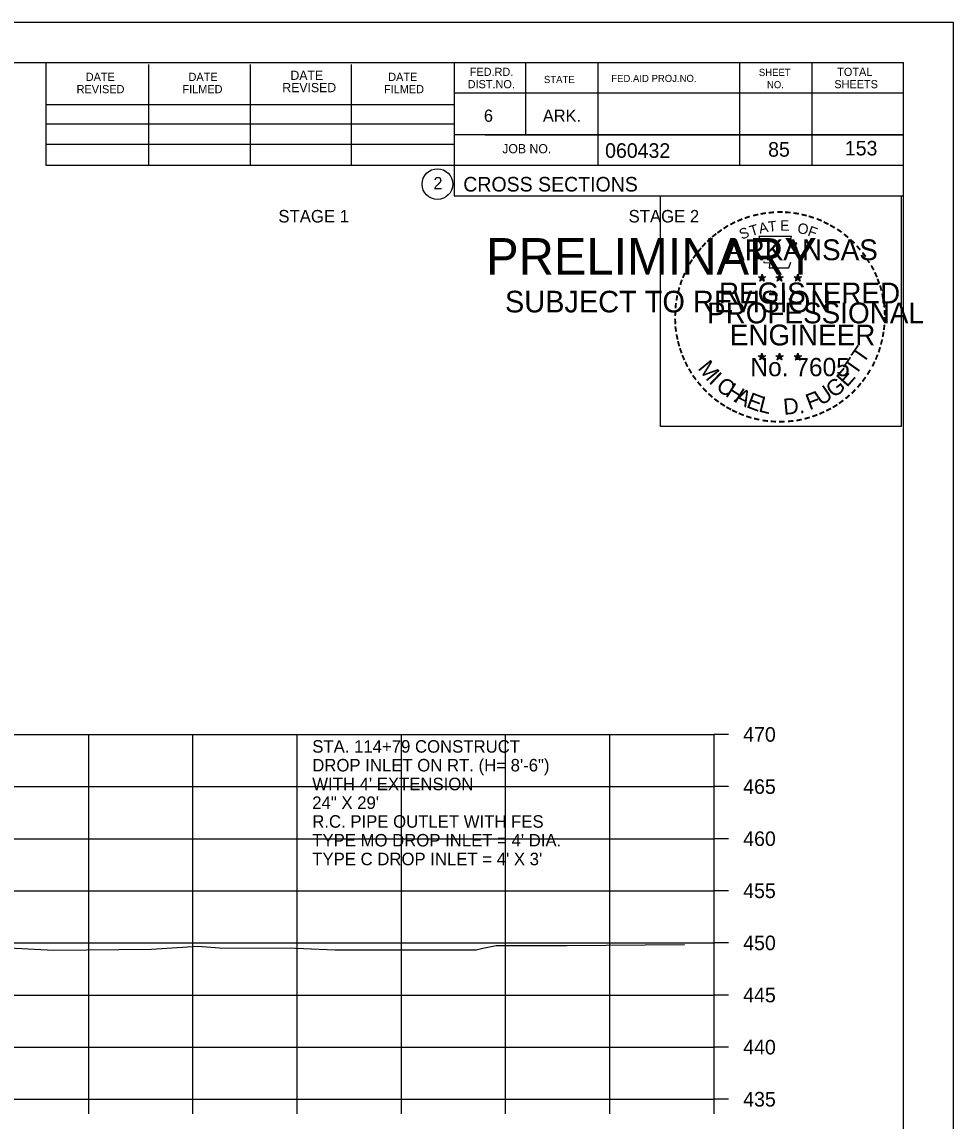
# Model space of a CAD drawing. Extents: x 1538688 to 1540766, y 656250 to 671912.
# Drawn here: x 1538931.8 to 1539021.1, y 658579.2 to 658684.6 of the extents above; entities that cross this region are included whole.
import ezdxf

# ---------------------------------------------------------------- set-up
doc = ezdxf.new("R2010")
doc.units = 0
for name, color, linetype in [('18', 7, 'Continuous'), ('22', 7, 'Continuous'), ('26', 7, 'Continuous'), ('40', 7, 'Continuous'), ('7', 7, 'Continuous'), ('8', 7, 'Continuous'), ('9', 7, 'Continuous'), ('Borings', 7, 'Continuous'), ('Default', 7, 'Continuous'), ('Horizontal Alignment', 7, 'Continuous'), ('RipRap', 7, 'Continuous')]:
    doc.layers.add(name, color=color, linetype=linetype)

msp = doc.modelspace()

# ---------------------------------------------------------------- linework, layer by layer
at = {"layer": '18'}
msp.add_lwpolyline([(1538918.78, 658596.39), (1538934.84, 658595.56), (1538944.21, 658595.67), (1538948.66, 658595.95), (1538950.74, 658595.79), (1538958.02, 658595.75), (1538961.83, 658595.6), (1538975.36, 658595.59), (1538976.01, 658595.74), (1538977.28, 658596.02), (1538984.07, 658596), (1538995.33, 658596.11)], dxfattribs=at)
at = {"layer": '22'}
for p, q in [((1538718.18, 658616.26), (1538998.18, 658616.26)), ((1538938.18, 658581.26), (1538938.18, 658616.26)), ((1538948.18, 658581.26), (1538948.18, 658616.26)), ((1538958.18, 658581.26), (1538958.18, 658616.26)), ((1538968.18, 658581.26), (1538968.18, 658616.26)), ((1538978.18, 658581.26), (1538978.18, 658616.26)), ((1538988.18, 658581.26), (1538988.18, 658616.26)), ((1538998.18, 658581.26), (1538998.18, 658616.26)), ((1538718.18, 658611.26), (1538998.18, 658611.26)), ((1538718.18, 658606.26), (1538998.18, 658606.26)), ((1538718.18, 658601.26), (1538998.18, 658601.26)), ((1538718.18, 658596.26), (1538998.18, 658596.26)), ((1538718.18, 658591.26), (1538998.18, 658591.26)), ((1538718.18, 658586.26), (1538998.18, 658586.26)), ((1538718.18, 658581.26), (1538998.18, 658581.26))]:
    msp.add_line(p, q, dxfattribs=at)
at = {"layer": '26'}
msp.add_line((1538687.78, 658684.61), (1539021.11, 658684.61), dxfattribs=at)
for points in [[(1538687.77, 658684.61), (1539021.11, 658684.61), (1539021.11, 658471.28), (1538687.77, 658471.28)], [(1538993.03, 658667.95), (1539016.13, 658667.95), (1539016.13, 658645.8), (1538993.03, 658645.8)]]:
    msp.add_lwpolyline(points, close=True, dxfattribs=at)
at = {"layer": '8'}
for p, q in [((1539002.44, 658660.17), (1539002.79, 658660.06)), ((1539002.44, 658660.17), (1539002.69, 658660.12)), ((1539002.44, 658660.17), (1539002.68, 658660.04)), ((1539002.57, 658659.76), (1539002.79, 658660.06)), ((1539002.57, 658659.76), (1539002.7, 658660)), ((1539002.57, 658659.76), (1539002.79, 658659.98)), ((1539002.79, 658660.42), (1539002.75, 658660.17)), ((1539002.79, 658660.06), (1539002.79, 658660.42)), ((1539002.79, 658660.42), (1539002.84, 658660.17)), ((1539003.13, 658660.17), (1539002.79, 658660.06)), ((1539003, 658659.76), (1539002.79, 658660.06)), ((1539003, 658659.76), (1539002.79, 658659.97)), ((1539003.13, 658660.17), (1539002.85, 658660.12)), ((1539003, 658659.76), (1539002.86, 658660.05)), ((1539003.13, 658660.17), (1539002.93, 658660.06)), ((1539004.11, 658660.17), (1539004.46, 658660.06)), ((1539004.11, 658660.17), (1539004.36, 658660.12)), ((1539004.11, 658660.17), (1539004.35, 658660.04)), ((1539004.24, 658659.76), (1539004.46, 658660.06)), ((1539004.24, 658659.76), (1539004.37, 658660)), ((1539004.24, 658659.76), (1539004.46, 658659.98)), ((1539004.46, 658660.42), (1539004.42, 658660.17)), ((1539004.46, 658660.06), (1539004.46, 658660.42)), ((1539004.46, 658660.42), (1539004.51, 658660.17)), ((1539004.8, 658660.17), (1539004.46, 658660.06)), ((1539004.67, 658659.76), (1539004.46, 658660.06)), ((1539004.67, 658659.76), (1539004.46, 658659.97)), ((1539004.8, 658660.17), (1539004.52, 658660.12)), ((1539004.67, 658659.76), (1539004.53, 658660.05)), ((1539004.8, 658660.17), (1539004.6, 658660.06)), ((1539005.87, 658660.15), (1539006.22, 658660.04)), ((1539005.87, 658660.15), (1539006.13, 658660.11)), ((1539005.87, 658660.15), (1539006.11, 658660.03)), ((1539006.01, 658659.75), (1539006.22, 658660.04)), ((1539006.01, 658659.75), (1539006.13, 658659.99)), ((1539006.01, 658659.75), (1539006.22, 658659.96)), ((1539006.22, 658660.41), (1539006.18, 658660.16)), ((1539006.22, 658660.04), (1539006.22, 658660.41)), ((1539006.22, 658660.41), (1539006.27, 658660.16)), ((1539006.57, 658660.15), (1539006.22, 658660.04)), ((1539006.43, 658659.75), (1539006.22, 658660.04)), ((1539006.43, 658659.75), (1539006.22, 658659.96)), ((1539006.57, 658660.15), (1539006.28, 658660.11)), ((1539006.43, 658659.75), (1539006.3, 658660.04)), ((1539006.57, 658660.15), (1539006.36, 658660.05)), ((1539002.43, 658652.59), (1539002.78, 658652.48)), ((1539002.43, 658652.59), (1539002.69, 658652.55)), ((1539002.43, 658652.59), (1539002.67, 658652.47)), ((1539002.57, 658652.19), (1539002.78, 658652.48)), ((1539002.57, 658652.19), (1539002.69, 658652.43)), ((1539002.57, 658652.19), (1539002.78, 658652.4)), ((1539002.78, 658652.85), (1539002.74, 658652.6)), ((1539002.78, 658652.48), (1539002.78, 658652.85)), ((1539002.78, 658652.85), (1539002.83, 658652.6)), ((1539003.13, 658652.59), (1539002.78, 658652.48)), ((1539003, 658652.19), (1539002.78, 658652.48)), ((1539003, 658652.19), (1539002.78, 658652.4)), ((1539003.13, 658652.59), (1539002.84, 658652.54)), ((1539003, 658652.19), (1539002.86, 658652.48)), ((1539003.13, 658652.59), (1539002.93, 658652.49)), ((1539004.1, 658652.59), (1539004.45, 658652.48)), ((1539004.1, 658652.59), (1539004.36, 658652.55)), ((1539004.1, 658652.59), (1539004.34, 658652.47)), ((1539004.24, 658652.19), (1539004.45, 658652.48)), ((1539004.24, 658652.19), (1539004.36, 658652.43)), ((1539004.24, 658652.19), (1539004.45, 658652.4)), ((1539004.45, 658652.85), (1539004.41, 658652.6)), ((1539004.45, 658652.48), (1539004.45, 658652.85)), ((1539004.45, 658652.85), (1539004.5, 658652.6)), ((1539004.8, 658652.59), (1539004.45, 658652.48)), ((1539004.67, 658652.19), (1539004.45, 658652.48)), ((1539004.67, 658652.19), (1539004.45, 658652.4)), ((1539004.8, 658652.59), (1539004.51, 658652.54)), ((1539004.67, 658652.19), (1539004.53, 658652.48)), ((1539004.8, 658652.59), (1539004.6, 658652.49)), ((1539005.87, 658652.58), (1539006.22, 658652.47)), ((1539005.87, 658652.58), (1539006.12, 658652.54)), ((1539005.87, 658652.58), (1539006.11, 658652.46)), ((1539006, 658652.18), (1539006.22, 658652.47)), ((1539006, 658652.18), (1539006.13, 658652.42)), ((1539006, 658652.18), (1539006.22, 658652.39)), ((1539006.22, 658652.84), (1539006.18, 658652.59)), ((1539006.22, 658652.47), (1539006.22, 658652.84)), ((1539006.22, 658652.84), (1539006.27, 658652.59)), ((1539006.57, 658652.58), (1539006.22, 658652.47)), ((1539006.43, 658652.18), (1539006.22, 658652.47)), ((1539006.43, 658652.18), (1539006.22, 658652.39)), ((1539006.57, 658652.58), (1539006.28, 658652.53)), ((1539006.43, 658652.18), (1539006.3, 658652.47)), ((1539006.57, 658652.58), (1539006.36, 658652.48))]:
    msp.add_line(p, q, dxfattribs=at)
for points in [[(1539002.48, 658664.04), (1539002.75, 658663.22)], [(1539005.99, 658663.12), (1539006.13, 658663.41), (1539005.45, 658663.38), (1539005.6, 658664.04), (1539002.48, 658664.04)], [(1539002.97, 658661.62), (1539002.97, 658661.53), (1539003.53, 658661.52), (1539003.48, 658661.04), (1539005.35, 658661.04), (1539005.55, 658661.58)], [(1539002.79, 658660.42), (1539003, 658659.76), (1539002.44, 658660.17), (1539003.13, 658660.17), (1539002.57, 658659.76), (1539002.79, 658660.42)], [(1539004.46, 658660.42), (1539004.67, 658659.76), (1539004.11, 658660.17), (1539004.8, 658660.17), (1539004.24, 658659.76), (1539004.46, 658660.42)], [(1539006.22, 658660.41), (1539006.43, 658659.75), (1539005.87, 658660.15), (1539006.57, 658660.15), (1539006.01, 658659.75), (1539006.22, 658660.41)], [(1539002.78, 658652.85), (1539003, 658652.19), (1539002.43, 658652.59), (1539003.13, 658652.59), (1539002.57, 658652.19), (1539002.78, 658652.85)], [(1539004.45, 658652.85), (1539004.67, 658652.19), (1539004.1, 658652.59), (1539004.8, 658652.59), (1539004.24, 658652.19), (1539004.45, 658652.85)], [(1539006.22, 658652.84), (1539006.43, 658652.18), (1539005.87, 658652.58), (1539006.57, 658652.58), (1539006, 658652.18), (1539006.22, 658652.84)]]:
    msp.add_lwpolyline(points, dxfattribs=at)
for centre, radius in [((1539002.79, 658660.06), 0.172), ((1539002.79, 658660.06), 0.145), ((1539002.79, 658660.06), 0.116), ((1539002.79, 658660.06), 0.0991), ((1539002.79, 658660.06), 0.0747), ((1539002.79, 658660.06), 0.0495), ((1539002.79, 658660.06), 0.0296), ((1539004.46, 658660.06), 0.172), ((1539004.46, 658660.06), 0.145), ((1539004.46, 658660.06), 0.116), ((1539004.46, 658660.06), 0.0991), ((1539004.46, 658660.06), 0.0747), ((1539004.46, 658660.06), 0.0495), ((1539004.46, 658660.06), 0.0296), ((1539006.22, 658660.04), 0.172), ((1539006.22, 658660.04), 0.145), ((1539006.22, 658660.04), 0.116), ((1539006.22, 658660.04), 0.0991), ((1539006.22, 658660.04), 0.0747), ((1539006.22, 658660.04), 0.0495), ((1539006.22, 658660.04), 0.0296), ((1539002.78, 658652.48), 0.172), ((1539002.78, 658652.48), 0.145), ((1539002.78, 658652.48), 0.116), ((1539002.78, 658652.48), 0.0991), ((1539002.78, 658652.48), 0.0747), ((1539002.78, 658652.48), 0.0495), ((1539002.78, 658652.48), 0.0296), ((1539004.45, 658652.48), 0.172), ((1539004.45, 658652.48), 0.145), ((1539004.45, 658652.48), 0.116), ((1539004.45, 658652.48), 0.0991), ((1539004.45, 658652.48), 0.0747), ((1539004.45, 658652.48), 0.0495), ((1539004.45, 658652.48), 0.0296), ((1539006.22, 658652.47), 0.172), ((1539006.22, 658652.47), 0.145), ((1539006.22, 658652.47), 0.116), ((1539006.22, 658652.47), 0.0991), ((1539006.22, 658652.47), 0.0747), ((1539006.22, 658652.47), 0.0495), ((1539006.22, 658652.47), 0.0296)]:
    msp.add_circle(centre, radius, dxfattribs=at)
at = {"layer": 'Borings'}
for p, q in [((1538998.18, 658581.26), (1538998.18, 658616.26)), ((1538999.58, 658616.26), (1538998.18, 658616.26)), ((1538999.58, 658611.26), (1538998.18, 658611.26)), ((1538999.58, 658606.26), (1538998.18, 658606.26)), ((1538999.58, 658601.26), (1538998.18, 658601.26)), ((1538999.58, 658596.26), (1538998.18, 658596.26)), ((1538999.58, 658591.26), (1538998.18, 658591.26)), ((1538999.58, 658586.26), (1538998.18, 658586.26)), ((1538718.18, 658581.26), (1538998.18, 658581.26)), ((1538938.18, 658579.86), (1538938.18, 658581.26)), ((1538948.18, 658579.86), (1538948.18, 658581.26)), ((1538958.18, 658579.86), (1538958.18, 658581.26)), ((1538968.18, 658579.86), (1538968.18, 658581.26)), ((1538978.18, 658579.86), (1538978.18, 658581.26)), ((1538988.18, 658579.86), (1538988.18, 658581.26)), ((1538998.18, 658579.86), (1538998.18, 658581.26)), ((1538999.58, 658581.26), (1538998.18, 658581.26))]:
    msp.add_line(p, q, dxfattribs=at)
at = {"layer": 'RipRap'}
for p, q in [((1538700.18, 658680.72), (1539016.36, 658680.72)), ((1538934.1, 658670.84), (1538934.1, 658680.72)), ((1538973.26, 658680.72), (1538973.26, 658667.92)), ((1538980.1, 658680.72), (1538980.1, 658673.78)), ((1538987.04, 658680.72), (1538987.04, 658670.84)), ((1539000.62, 658680.72), (1539000.62, 658670.84)), ((1539007.56, 658680.72), (1539007.56, 658670.84)), ((1539016.36, 658475.26), (1539016.36, 658680.72)), ((1538943.96, 658670.84), (1538943.96, 658680.52)), ((1538953.72, 658670.84), (1538953.72, 658680.52)), ((1538963.4, 658670.84), (1538963.4, 658680.52)), ((1539016.36, 658677.78), (1538973.26, 658677.78)), ((1539016.36, 658677.8), (1539016.36, 658677.8)), ((1538934.1, 658676.7), (1538973.26, 658676.7)), ((1538934.1, 658674.84), (1538973.26, 658674.84)), ((1539016.36, 658673.78), (1538973.26, 658673.78)), ((1538976.22, 658673.78), (1539016.36, 658673.78)), ((1538934.1, 658670.84), (1538934.1, 658672.9)), ((1538934.1, 658672.9), (1538973.26, 658672.9)), ((1539016.36, 658670.84), (1538934.1, 658670.84)), ((1538973.26, 658667.92), (1539016.36, 658667.92))]:
    msp.add_line(p, q, dxfattribs=at)
msp.add_circle((1538971.64, 658669.06), 1.47, dxfattribs=at)

# ---------------------------------------------------------------- texts
at = {"layer": '40'}
for s, p in [('STA. 114+79 CONSTRUCT', (1538959.63, 658614.51)), ('DROP INLET ON RT. (H= 8\'-6") ', (1538959.63, 658612.71)), ("WITH 4' EXTENSION ", (1538959.63, 658610.91)), ('24" X 29\'', (1538959.63, 658609.11)), ('R.C. PIPE OUTLET WITH FES', (1538959.63, 658607.31)), ("TYPE MO DROP INLET = 4' DIA.", (1538959.63, 658605.51)), ("TYPE C DROP INLET = 4' X 3'", (1538959.63, 658603.71))]:
    msp.add_text(s, height=1.2, dxfattribs=at).set_placement(p)
at = {"layer": '7'}
for s, p in [('153', (1539010.73, 658671.81)), ('85', (1539003.37, 658671.69))]:
    msp.add_text(s, height=1.4, dxfattribs=at).set_placement(p)
at = {"layer": '8'}
for s, height, rotation, p in [('-', 1.6, 24.3072, (1539000.59, 658664.9)), ('-', 1.6, 19.1761, (1539001.23, 658665.17)), ('-', 1.6, 13.6301, (1539001.98, 658665.41)), ('-', 1.6, 10.2193, (1539002.66, 658665.57)), ('-', 1.6, 5.8968, (1539003.38, 658665.68)), ('-', 1.6, 0.1862, (1539004.16, 658665.76)), ('-', 1.6, 357.743, (1539004.88, 658665.74)), ('-', 1.6, 352.1617, (1539005.62, 658665.69)), ('-', 1.6, 347.2049, (1539006.34, 658665.57)), ('-', 1.6, 342.3362, (1539006.98, 658665.42)), ('-', 1.6, 337.8551, (1539007.71, 658665.2)), ('-', 1.6, 36.2317, (1538998.79, 658663.82)), ('-', 1.6, 34.0636, (1538999.36, 658664.22)), ('-', 1.6, 28.7918, (1538999.96, 658664.59)), ('S', 1, 21.594, (1539000.83, 658663.72)), ('T', 1, 16.4036, (1539001.75, 658664.05)), ('A', 1, 11.2132, (1539002.57, 658664.3)), ('T', 1, 6.0228, (1539003.42, 658664.47)), ('E', 1, 0.8323, (1539004.53, 658664.58)), ('O', 1, 350.4515, (1539006.13, 658664.37)), ('F', 1, 340.0707, (1539007.09, 658664.14)), ('-', 1.6, 334.1211, (1539008.34, 658664.92)), ('-', 1.6, 329.6409, (1539008.92, 658664.64)), ('-', 1.6, 325.8627, (1539009.57, 658664.28)), ('-', 1.6, 42.9622, (1538997.88, 658663.03)), ('-', 1.6, 38.9507, (1538998.31, 658663.44)), ('ARKANSAS', 2, 360, (1538999.33, 658661.76)), ('-', 1.6, 320.5297, (1539010.18, 658663.85)), ('-', 1.6, 315.5786, (1539010.77, 658663.37)), ('-', 1.6, 50.6142, (1538997.03, 658662.06)), ('-', 1.6, 48.423, (1538997.43, 658662.55)), ('-', 1.6, 309.8797, (1539011.34, 658662.82)), ('-', 1.6, 58.0706, (1538996.29, 658660.97)), ('-', 1.6, 54.2325, (1538996.61, 658661.49)), ('-', 1.6, 306.6522, (1539011.87, 658662.21)), ('-', 1.4, 303.6753, (1539012.35, 658661.65)), ('-', 1.6, 67.7743, (1538995.72, 658659.74)), ('-', 1.6, 62.8713, (1538995.97, 658660.35)), ('-', 1.6, 299.6684, (1539012.67, 658661.04)), ('-', 1.6, 294.6628, (1539013, 658660.43)), ('-', 1.6, 72.3945, (1538995.5, 658659.11)), ('REGISTERED', 2, 360, (1538998.65, 658657.61)), ('DWB', 0.01, 360, (1539002.77, 658660.05)), ('DWB', 0.01, 360, (1539004.44, 658660.05)), ('DWB', 0.01, 360, (1539006.21, 658660.04)), ('-', 1.6, 290.5728, (1539013.25, 658659.85)), ('-', 1.6, 75.461, (1538995.3, 658658.4)), ('-', 1.6, 285.1233, (1539013.49, 658659.27)), ('-', 1.6, 280.5493, (1539013.69, 658658.53)), ('-', 1.6, 85.1863, (1538995.09, 658656.99)), ('-', 1.6, 81.2013, (1538995.17, 658657.69)), ('PROFESSIONAL', 2, 360, (1538997.51, 658655.7)), ('-', 1.6, 276.5962, (1539013.85, 658657.76)), ('-', 1.6, 89.0622, (1538995.07, 658656.29)), ('-', 1.6, 274.3301, (1539013.91, 658657.04)), ('-', 1.6, 269.9407, (1539013.94, 658656.41)), ('-', 1.6, 94.1959, (1538995.1, 658655.57)), ('-', 1.6, 98.9479, (1538995.17, 658654.9)), ('ENGINEER', 2, 360, (1538999.69, 658653.58)), ('-', 1.6, 263.5172, (1539013.93, 658655.74)), ('-', 1.6, 101.7149, (1538995.31, 658654.17)), ('-', 1.6, 260.9953, (1539013.85, 658655.09)), ('-', 1.6, 105.4578, (1538995.47, 658653.57)), ('-', 1.6, 109.0874, (1538995.69, 658652.94)), ('T', 1.54, 55.055, (1539012.5, 658651.75)), ('-', 1.6, 252.8681, (1539013.56, 658653.69)), ('-', 1.6, 255.7626, (1539013.74, 658654.41)), ('-', 1.6, 114.0643, (1538995.94, 658652.35)), ('M', 1.54, 308.9175, (1538996.55, 658651.37)), ('No. 7605', 1.757, 360, (1539001.67, 658650.63)), ('DWB', 0.01, 360, (1539002.77, 658652.48)), ('DWB', 0.01, 360, (1539004.44, 658652.48)), ('DWB', 0.01, 360, (1539006.2, 658652.47)), ('T', 1.54, 55.055, (1539011.77, 658650.63)), ('-', 1.6, 247.8887, (1539013.34, 658653.02)), ('-', 1.6, 115.7289, (1538996.24, 658651.73)), ('-', 1.6, 120.4471, (1538996.6, 658651.14)), ('I', 1.54, 316.4636, (1538997.6, 658650.05)), ('E', 1.54, 48.7313, (1539010.93, 658649.5)), ('-', 1.6, 239.0712, (1539012.68, 658651.63)), ('-', 1.6, 244.6197, (1539013.08, 658652.39)), ('-', 1.6, 125.8934, (1538997, 658650.58)), ('-', 1.6, 130.7181, (1538997.47, 658650.03)), ('C', 1.54, 324.0197, (1538998.27, 658649.43)), ('H', 1.54, 327.5342, (1538999.18, 658648.78)), ('G', 1.54, 38.2173, (1539009.67, 658648.48)), ('-', 1.6, 231.2538, (1539011.85, 658650.42)), ('-', 1.6, 233.8452, (1539012.28, 658650.98)), ('-', 1.6, 134.2238, (1538997.98, 658649.48)), ('-', 1.6, 138.9338, (1538998.51, 658649.02)), ('A', 1.54, 332.5513, (1539000.03, 658648.24)), ('E', 1.54, 339.2068, (1539001.19, 658647.68)), ('F', 1.54, 20.8202, (1539007.34, 658647.35)), ('U', 1.54, 34.4052, (1539008.47, 658647.75)), ('-', 1.6, 225.7653, (1539011.37, 658649.85)), ('-', 1.6, 144.6463, (1538999.06, 658648.61)), ('-', 1.6, 148.0898, (1538999.63, 658648.24)), ('L', 1.54, 346.2929, (1539002.38, 658647.25)), ('D.', 1.54, 5.2602, (1539004.89, 658646.92)), ('-', 1.6, 212.2491, (1539009.77, 658648.48)), ('-', 1.6, 215.7363, (1539010.3, 658648.87)), ('-', 1.6, 221.0851, (1539010.85, 658649.34)), ('-', 1.6, 151.5704, (1539000.2, 658647.92)), ('-', 1.6, 154.6002, (1539000.73, 658647.67)), ('-', 1.6, 158.5612, (1539001.35, 658647.42)), ('-', 1.6, 162.7983, (1539002.04, 658647.2)), ('-', 1.6, 200.7184, (1539007.97, 658647.55)), ('-', 1.6, 204.2516, (1539008.59, 658647.82)), ('-', 1.6, 207.3568, (1539009.21, 658648.14)), ('-', 1.6, 167.5555, (1539002.75, 658647.04)), ('-', 1.6, 173.1155, (1539003.52, 658646.93)), ('-', 1.6, 176.5183, (1539004.27, 658646.88)), ('-', 1.6, 181.5918, (1539005.02, 658646.9)), ('-', 1.6, 185.8167, (1539005.83, 658646.97)), ('-', 1.6, 191.2858, (1539006.56, 658647.1)), ('-', 1.6, 195.4743, (1539007.29, 658647.3))]:
    msp.add_text(s, height=height, rotation=rotation, dxfattribs=at).set_placement(p)
at = {"layer": '9'}
for s, height, p in [('PRELIMINARY', 3.5, (1538976.31, 658660.38)), ('DWB', 0.01, (1538977.06, 658662.23)), ('SUBJECT TO REVISION', 2.0751, (1538978.12, 658656.75))]:
    msp.add_text(s, height=height, rotation=360, dxfattribs=at).set_placement(p)
at = {"layer": 'Default'}
for s, p in [('STAGE 1', (1538956.38, 658665.38)), ('STAGE 2', (1538989.98, 658665.38))]:
    msp.add_text(s, height=1.2, dxfattribs=at).set_placement(p)
at = {"layer": 'Horizontal Alignment'}
for s, p in [('470', (1539000.98, 658615.56)), ('465', (1539000.98, 658610.56)), ('460', (1539000.98, 658605.56)), ('455', (1539000.98, 658600.56)), ('450', (1539000.98, 658595.56)), ('445', (1539000.98, 658590.56)), ('440', (1539000.98, 658585.56)), ('435', (1539000.98, 658580.56))]:
    msp.add_text(s, height=1.4, dxfattribs=at).set_placement(p)
at = {"layer": 'RipRap'}
for s, height, p in [('DATE', 0.782, (1538937.9, 658678.96)), ('DATE', 0.782, (1538947.76, 658678.96)), ('DATE', 0.879, (1538957.54, 658679.06)), ('DATE', 0.782, (1538966.92, 658678.96)), ('FED.RD.', 0.782, (1538974.74, 658679.44)), ('FED.AID PROJ.NO.', 0.684, (1538988.32, 658678.86)), ('SHEET', 0.684, (1539002.48, 658679.44)), ('TOTAL', 0.782, (1539010, 658679.44)), ('REVISED', 0.782, (1538937.02, 658677.78)), ('FILMED', 0.782, (1538947.18, 658677.78)), ('REVISED', 0.879, (1538956.76, 658677.88)), ('FILMED', 0.782, (1538966.52, 658677.78)), ('DIST.NO.', 0.782, (1538974.54, 658678.26)), ('STATE', 0.684, (1538981.86, 658678.76)), ('NO.', 0.684, (1539003.26, 658678.26)), ('SHEETS', 0.782, (1539009.72, 658678.26)), ('6', 1.17, (1538976.1, 658675.04)), ('ARK.', 1.172, (1538981.76, 658675.04)), ('JOB NO.', 0.879, (1538977.86, 658672.02)), ('060432', 1.4, (1538987.73, 658671.58)), ('2', 1.17, (1538971.26, 658668.57)), ('CROSS SECTIONS', 1.4, (1538974.12, 658668.35))]:
    msp.add_text(s, height=height, rotation=360, dxfattribs=at).set_placement(p)

doc.saveas('drawing.dxf')
